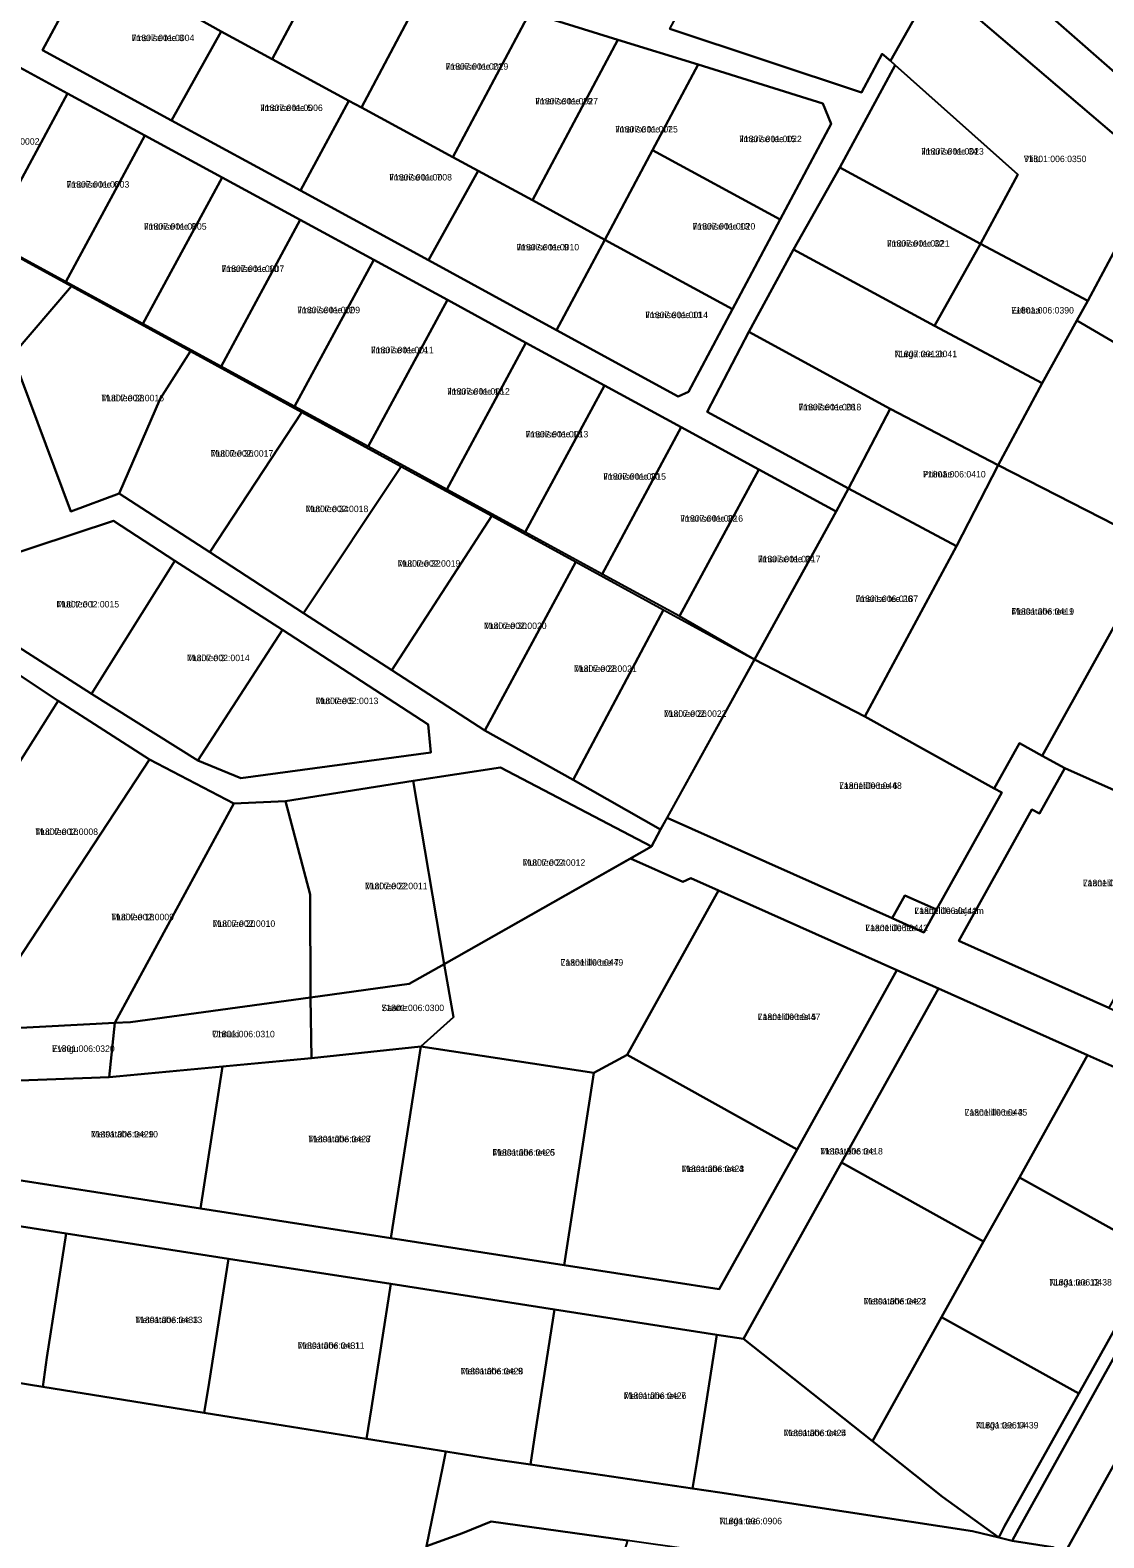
# Model space of a CAD drawing. Extents: x 529768 to 552006, y 6562269 to 6580975.
# Drawn here: x 538116.9 to 538365.3, y 6569572.9 to 6569921.8 of the extents above; entities that cross this region are included whole.
import ezdxf

# ---------------------------------------------------------------- set-up
doc = ezdxf.new("R2010")
doc.units = 0
for name, color, linetype in [('L_AADRESS', 7, 'Continuous'), ('PIIR', 7, 'Continuous'), ('TUNNUS', 7, 'Continuous')]:
    doc.layers.add(name, color=color, linetype=linetype)

msp = doc.modelspace()

# ---------------------------------------------------------------- linework, layer by layer
at = {"layer": 'PIIR'}
for points in [[(538194.78, 6570045.29), (538204.09, 6570052.49), (538294.54, 6569976.3), (538387.81, 6569894.55), (538483.98, 6569812.62), (538481.98, 6569810.6), (538469.84, 6569798.25), (538468.86, 6569806.04), (538468.33, 6569807.76), (538466.92, 6569812.96), (538412.51, 6569859.39), (538377.69, 6569889.12), (538326.28, 6569933.03), (538292.44, 6569961.91), (538270.33, 6569980.79), (538256.38, 6569992.7), (538223.22, 6570021.01)], [(538130.09, 6569936.52), (538119.74, 6569917.12), (538149.59, 6569900.87), (538179.4, 6569884.65), (538209.01, 6569868.54), (538238.69, 6569852.39), (538266.8, 6569836.99), (538269.18, 6569838.12), (538279.4, 6569857.26), (538290.44, 6569877.94), (538302.25, 6569900.12), (538300.32, 6569904.83), (538271.42, 6569913.8), (538252.85, 6569919.57), (538232.51, 6569925.89), (538209.07, 6569933.17), (538191.16, 6569949.28), (538176.18, 6569962.9), (538170.92, 6569967.63), (538167.9, 6569967.7), (538131.41, 6569937.62)], [(538161.09, 6569921.5), (538155.82, 6569924.37), (538176.18, 6569962.9), (538191.16, 6569949.28), (538172.87, 6569915.11)], [(538278.76, 6569947.68), (538292.44, 6569961.91), (538326.28, 6569933.03), (538315.93, 6569914.67), (538314.05, 6569916.29), (538309.25, 6569907.34), (538264.92, 6569922.07)], [(538190.61, 6569905.47), (538172.87, 6569915.11), (538191.16, 6569949.28), (538209.07, 6569933.17), (538193.51, 6569903.91)], [(538155.82, 6569924.37), (538161.09, 6569921.5), (538149.59, 6569900.87), (538119.74, 6569917.12), (538130.09, 6569936.52), (538131.41, 6569937.62)], [(538214.69, 6569892.4), (538193.51, 6569903.91), (538209.07, 6569933.17), (538232.51, 6569925.89)], [(538345.46, 6569888.38), (538317.02, 6569913.66), (538315.93, 6569914.67), (538326.28, 6569933.03), (538377.69, 6569889.14), (538361.67, 6569859.15), (538336.78, 6569872.31)], [(538232.51, 6569925.89), (538252.85, 6569919.57), (538233.08, 6569882.41), (538220.51, 6569889.24), (538214.69, 6569892.4)], [(538172.87, 6569915.11), (538190.61, 6569905.47), (538179.4, 6569884.65), (538149.59, 6569900.87), (538161.09, 6569921.5)], [(538105.9, 6569917.81), (538125.49, 6569907.16), (538107.21, 6569873.27), (538083.52, 6569886.17)], [(538252.85, 6569919.57), (538271.42, 6569913.8), (538260.89, 6569894.03), (538249.87, 6569873.3), (538233.08, 6569882.41)], [(538300.32, 6569904.83), (538302.25, 6569900.12), (538290.44, 6569877.94), (538260.89, 6569894.03), (538271.42, 6569913.8)], [(538317.02, 6569913.66), (538345.46, 6569888.38), (538336.78, 6569872.31), (538304.21, 6569890.03)], [(538125.49, 6569907.16), (538143.39, 6569897.43), (538125.1, 6569863.53), (538107.21, 6569873.27)], [(538179.4, 6569884.65), (538190.61, 6569905.47), (538193.51, 6569903.91), (538214.69, 6569892.4), (538220.51, 6569889.24), (538209.01, 6569868.54)], [(538143.39, 6569897.43), (538161.27, 6569887.71), (538142.97, 6569853.8), (538125.1, 6569863.53)], [(538249.87, 6569873.3), (538260.89, 6569894.03), (538290.44, 6569877.94), (538279.4, 6569857.26)], [(538209.01, 6569868.54), (538220.51, 6569889.24), (538233.08, 6569882.41), (538249.87, 6569873.3), (538238.69, 6569852.39)], [(538293.52, 6569871.07), (538304.21, 6569890.03), (538336.78, 6569872.31), (538326.18, 6569853.35)], [(538361.67, 6569859.15), (538377.69, 6569889.14), (538412.51, 6569859.39), (538410.45, 6569857.04), (538391.66, 6569835.55), (538359.11, 6569854.57)], [(538142.97, 6569853.8), (538161.27, 6569887.71), (538179.34, 6569877.88), (538161.04, 6569843.96)], [(538161.04, 6569843.96), (538179.34, 6569877.88), (538196.37, 6569868.62), (538178.07, 6569834.69)], [(538279.4, 6569857.26), (538269.18, 6569838.12), (538266.8, 6569836.99), (538238.69, 6569852.39), (538249.87, 6569873.3)], [(538336.78, 6569872.31), (538361.67, 6569859.15), (538359.11, 6569854.57), (538351.09, 6569840.13), (538326.18, 6569853.35)], [(538178.07, 6569834.69), (538196.37, 6569868.62), (538213.41, 6569859.36), (538195.1, 6569825.42)], [(538293.52, 6569871.07), (538326.18, 6569853.35), (538351.09, 6569840.13), (538340.87, 6569821.17), (538315.9, 6569834.2), (538283.19, 6569851.95)], [(538112.75, 6569846.55), (538126.45, 6569862.56), (538153.93, 6569847.53), (538146.92, 6569836.49), (538137.49, 6569814.61), (538126.26, 6569810.39)], [(538195.1, 6569825.42), (538213.41, 6569859.36), (538231.59, 6569849.47), (538213.27, 6569815.52)], [(538351.09, 6569840.13), (538359.11, 6569854.57), (538391.66, 6569835.55), (538374.81, 6569803.78), (538340.87, 6569821.17)], [(538315.9, 6569834.2), (538306.24, 6569815.71), (538273.53, 6569833.51), (538283.19, 6569851.95)], [(538137.49, 6569814.61), (538146.92, 6569836.49), (538153.93, 6569847.53), (538179.75, 6569833.42), (538158.46, 6569801)], [(538213.27, 6569815.52), (538231.59, 6569849.47), (538249.77, 6569839.58), (538231.45, 6569805.62)], [(538231.45, 6569805.62), (538249.77, 6569839.58), (538267.55, 6569829.91), (538249.22, 6569795.94)], [(538179.75, 6569833.42), (538202.75, 6569820.85), (538180.13, 6569786.88), (538158.46, 6569801)], [(538315.9, 6569834.2), (538340.87, 6569821.17), (538331.25, 6569802.37), (538306.24, 6569815.71)], [(538249.22, 6569795.94), (538267.55, 6569829.91), (538285.47, 6569820.17), (538267.13, 6569786.19)], [(538180.13, 6569786.88), (538202.75, 6569820.85), (538223.68, 6569809.4), (538200.59, 6569773.67)], [(538267.13, 6569786.19), (538285.47, 6569820.17), (538303.39, 6569810.42), (538284.49, 6569776.16)], [(538340.87, 6569821.17), (538374.81, 6569803.78), (538377.9, 6569802.16), (538351.04, 6569753.92), (538345.8, 6569756.83), (538339.96, 6569746.35), (538310.01, 6569763.02), (538331.25, 6569802.37)], [(538284.49, 6569776.16), (538303.39, 6569810.42), (538306.24, 6569815.71), (538331.25, 6569802.37), (538310.01, 6569763.02)], [(538200.59, 6569773.67), (538223.68, 6569809.4), (538243.17, 6569798.75), (538222.05, 6569759.71)], [(538481.98, 6569810.6), (538487.63, 6569805.85), (538461.57, 6569758.92), (538458.39, 6569753.08), (538452.57, 6569742.7), (538433.7, 6569708.78), (538415.11, 6569675.33), (538409.28, 6569664.76), (538391.55, 6569632.83), (538374.35, 6569601.84), (538359.18, 6569574.54), (538356.27, 6569569.3), (538353.57, 6569570.8), (538344.1, 6569572.28), (538345.65, 6569575.1), (538450.76, 6569763.95), (538469.84, 6569798.25)], [(538136.16, 6569808.23), (538150.33, 6569799.01), (538131.06, 6569768.19), (538103.29, 6569785.94), (538098.94, 6569796.03)], [(538155.69, 6569752.8), (538165.61, 6569748.68), (538209.61, 6569754.66), (538208.94, 6569761.16), (538175.26, 6569783.01), (538150.33, 6569799.01), (538136.16, 6569808.23), (538098.94, 6569796.03), (538103.29, 6569785.94), (538131.06, 6569768.19)], [(538377.9, 6569802.16), (538397.21, 6569792.04), (538414.99, 6569782.72), (538399.06, 6569754.1), (538389.18, 6569736.34), (538356.29, 6569751), (538351.04, 6569753.92)], [(538150.33, 6569799.01), (538175.26, 6569783.01), (538155.69, 6569752.8), (538131.06, 6569768.19)], [(538222.05, 6569759.71), (538243.17, 6569798.75), (538263.42, 6569787.68), (538242.55, 6569748.31)], [(538263.42, 6569787.68), (538284.49, 6569776.16), (538262.76, 6569736.8), (538242.55, 6569748.31)], [(538073.96, 6569739.47), (538100.97, 6569781.45), (538123.36, 6569766.57), (538091.68, 6569716.58)], [(538175.26, 6569783.01), (538208.94, 6569761.16), (538209.61, 6569754.66), (538165.61, 6569748.68), (538155.69, 6569752.8)], [(538284.49, 6569776.16), (538310.01, 6569763.02), (538339.96, 6569746.35), (538341.71, 6569745.38), (538326.63, 6569718.29), (538319.3, 6569721.55), (538316.37, 6569716.29), (538264.26, 6569739.51)], [(538091.68, 6569716.58), (538123.36, 6569766.57), (538144.44, 6569753.03), (538107.27, 6569696.53)], [(538448.11, 6569765.36), (538450.76, 6569763.95), (538345.65, 6569575.1), (538344.1, 6569572.28), (538341.05, 6569573.02), (538342.38, 6569575.61), (538359.59, 6569606.32), (538377.59, 6569638.65), (538394.92, 6569669.8), (538400.66, 6569680.38), (538415.6, 6569707.13), (538431.68, 6569735.94)], [(538264.26, 6569739.51), (538316.37, 6569716.29), (538323.7, 6569713.02), (538326.63, 6569718.29), (538341.71, 6569745.38), (538339.96, 6569746.35), (538345.8, 6569756.83), (538351.04, 6569753.92), (538356.29, 6569751), (538350.45, 6569740.51), (538348.7, 6569741.49), (538331.77, 6569711.07), (538366.5, 6569695.6), (538400.66, 6569680.38), (538394.92, 6569669.8), (538361.56, 6569684.66), (538327.06, 6569700.03), (538317.43, 6569704.32), (538276.16, 6569722.71), (538269.78, 6569725.55), (538267.89, 6569724.75), (538255.8, 6569730.14), (538260.66, 6569732.9), (538262.76, 6569736.8)], [(538107.27, 6569696.53), (538144.44, 6569753.03), (538164.01, 6569742.86), (538136.43, 6569692.07), (538111.76, 6569690.76)], [(538205.51, 6569748.11), (538225.68, 6569751.2), (538260.66, 6569732.9), (538212.68, 6569705.68)], [(538356.29, 6569751), (538389.18, 6569736.34), (538383.01, 6569725.26), (538366.5, 6569695.6), (538331.77, 6569711.07), (538348.7, 6569741.49), (538350.45, 6569740.51)], [(538181.63, 6569721.82), (538175.98, 6569743.41), (538205.51, 6569748.11), (538212.68, 6569705.68), (538204.6, 6569701.11), (538181.7, 6569697.97)], [(538164.01, 6569742.86), (538175.98, 6569743.41), (538181.63, 6569721.82), (538181.7, 6569697.97), (538140.09, 6569692.27), (538136.43, 6569692.07)], [(538212.68, 6569705.68), (538255.8, 6569730.14), (538267.89, 6569724.75), (538269.78, 6569725.55), (538276.16, 6569722.71), (538255.01, 6569684.7), (538247.32, 6569680.53), (538207.24, 6569686.64), (538214.81, 6569693.44)], [(538276.16, 6569722.71), (538317.43, 6569704.32), (538294.33, 6569662.81), (538255.01, 6569684.7)], [(538319.3, 6569721.55), (538326.63, 6569718.29), (538323.7, 6569713.02), (538316.37, 6569716.29)], [(538080.43, 6569660.96), (538101.78, 6569657.64), (538156.29, 6569649.16), (538200.35, 6569642.31), (538240.41, 6569636.07), (538276.33, 6569630.48), (538294.33, 6569662.81), (538317.43, 6569704.32), (538327.06, 6569700.03), (538304.66, 6569659.78), (538281.95, 6569618.98), (538275.78, 6569619.94), (538238.23, 6569625.78), (538200.29, 6569631.68), (538162.74, 6569637.52), (538125.19, 6569643.36), (538092.65, 6569648.42), (538092.11, 6569644.96), (538078.27, 6569647.11)], [(538204.6, 6569701.11), (538212.68, 6569705.68), (538214.81, 6569693.44), (538207.24, 6569686.64), (538181.94, 6569683.95), (538181.7, 6569697.97)], [(538136.43, 6569692.07), (538140.09, 6569692.27), (538181.7, 6569697.97), (538181.94, 6569683.95), (538135.13, 6569679.55)], [(538327.06, 6569700.03), (538361.56, 6569684.66), (538345.8, 6569656.34), (538337.53, 6569641.48), (538304.66, 6569659.78)], [(538105.49, 6569681.5), (538111.76, 6569690.76), (538136.43, 6569692.07), (538135.13, 6569679.55), (538112.43, 6569678.68)], [(538161.4, 6569682.02), (538181.94, 6569683.95), (538207.24, 6569686.64), (538200.35, 6569642.31), (538156.29, 6569649.16)], [(538207.24, 6569686.64), (538247.32, 6569680.53), (538240.41, 6569636.07), (538200.35, 6569642.31)], [(538247.32, 6569680.53), (538255.01, 6569684.7), (538294.33, 6569662.81), (538276.33, 6569630.48), (538240.41, 6569636.07)], [(538361.56, 6569684.66), (538394.92, 6569669.8), (538377.59, 6569638.65), (538345.8, 6569656.34)], [(538105.49, 6569681.5), (538112.43, 6569678.68), (538135.13, 6569679.55), (538161.4, 6569682.02), (538156.29, 6569649.16), (538101.78, 6569657.64)], [(538304.66, 6569659.78), (538337.53, 6569641.48), (538327.8, 6569624.01), (538311.83, 6569595.3), (538281.95, 6569618.98)], [(538345.8, 6569656.34), (538377.59, 6569638.65), (538359.59, 6569606.32), (538327.8, 6569624.01), (538337.53, 6569641.48)], [(538078.27, 6569647.11), (538092.11, 6569644.96), (538092.65, 6569648.42), (538125.19, 6569643.36), (538120.73, 6569614.69), (538119.76, 6569607.91), (538112.71, 6569609.04), (538093.34, 6569612.14), (538073.31, 6569615.34), (538074.42, 6569622.33)], [(538125.19, 6569643.36), (538162.74, 6569637.52), (538158.28, 6569608.86), (538157.16, 6569601.9), (538119.76, 6569607.91), (538120.73, 6569614.69)], [(538158.28, 6569608.86), (538162.74, 6569637.52), (538200.29, 6569631.68), (538195.83, 6569603.03), (538194.71, 6569595.86), (538169.62, 6569599.89), (538157.16, 6569601.9)], [(538200.29, 6569631.68), (538238.23, 6569625.78), (538233.77, 6569597.13), (538232.64, 6569589.88), (538225.06, 6569590.99), (538194.71, 6569595.86), (538195.83, 6569603.03)], [(538238.23, 6569625.78), (538275.78, 6569619.94), (538271.32, 6569591.29), (538270.16, 6569584.4), (538232.64, 6569589.88), (538233.77, 6569597.13)], [(538327.8, 6569624.01), (538359.59, 6569606.32), (538342.38, 6569575.61), (538341.05, 6569573.02), (538328.01, 6569582.47), (538311.83, 6569595.3)], [(538270.16, 6569584.4), (538271.32, 6569591.29), (538275.78, 6569619.94), (538281.95, 6569618.98), (538311.83, 6569595.3), (538328.01, 6569582.47), (538341.05, 6569573.02), (538334.93, 6569574.49), (538276.48, 6569583.47)], [(538374.35, 6569601.84), (538405.82, 6569584.36), (538390.33, 6569556.47), (538387.81, 6569551.93), (538356.27, 6569569.3), (538359.18, 6569574.54)], [(538212.36, 6569589.46), (538213.06, 6569592.91), (538225.06, 6569590.99), (538232.64, 6569589.88), (538270.16, 6569584.4), (538276.48, 6569583.47), (538334.93, 6569574.49), (538341.05, 6569573.02), (538344.1, 6569572.28), (538353.57, 6569570.8), (538352.24, 6569568.28), (538347.47, 6569559.27), (538343.28, 6569559.86), (538299.59, 6569566.02), (538255.09, 6569572.3), (538223.52, 6569576.75), (538216.9, 6569574.06), (538208.58, 6569571.04)], [(538208.58, 6569571.04), (538216.9, 6569574.06), (538223.52, 6569576.75), (538255.09, 6569572.3), (538198.64, 6569390.2), (538173.96, 6569399.94)]]:
    msp.add_lwpolyline(points, close=True, dxfattribs=at)
for points in [[(538463.69, 6569930.51), (538500.26, 6569829.22), (538483.98, 6569812.62), (538387.81, 6569894.55), (538294.54, 6569976.3)], [(538264.92, 6569922.07), (538309.25, 6569907.34), (538314.05, 6569916.29), (538315.93, 6569914.67), (538317.02, 6569913.66), (538304.21, 6569890.03), (538293.52, 6569871.07), (538283.19, 6569851.95), (538273.53, 6569833.51), (538306.24, 6569815.71), (538303.39, 6569810.42), (538285.47, 6569820.17), (538267.55, 6569829.91), (538249.77, 6569839.58), (538231.59, 6569849.47), (538213.41, 6569859.36), (538196.37, 6569868.62), (538179.34, 6569877.88), (538161.27, 6569887.71), (538143.39, 6569897.43), (538125.49, 6569907.16), (538105.9, 6569917.81)], [(538033.76, 6569913.23), (538126.45, 6569862.56), (538112.75, 6569846.55), (538126.26, 6569810.39), (538137.49, 6569814.61), (538158.46, 6569801), (538180.13, 6569786.88), (538200.59, 6569773.67), (538222.05, 6569759.71), (538242.55, 6569748.31), (538262.76, 6569736.8), (538260.66, 6569732.9), (538225.68, 6569751.2), (538205.51, 6569748.11), (538175.98, 6569743.41), (538164.01, 6569742.86), (538144.44, 6569753.03), (538123.36, 6569766.57), (538100.97, 6569781.45)], [(538112.71, 6569609.04), (538119.76, 6569607.91), (538157.16, 6569601.9), (538169.62, 6569599.89), (538194.71, 6569595.86), (538213.06, 6569592.91), (538212.36, 6569589.46), (538208.58, 6569571.04), (538173.96, 6569399.94), (538198.64, 6569390.2), (538221.78, 6569381.06), (538236.86, 6569375.1), (538239.69, 6569373.99), (538240.87, 6569373.65), (538242.38, 6569373.72), (538244.02, 6569374.31), (538245.03, 6569375.08), (538245.95, 6569376.29), (538343.28, 6569559.86), (538347.47, 6569559.27), (538262.64, 6569398.41), (538232.72, 6569343.23), (538167.92, 6569228.94), (538087.24, 6569085.89)]]:
    msp.add_lwpolyline(points, dxfattribs=at)

# ---------------------------------------------------------------- texts
at = {"layer": 'L_AADRESS'}
for s, p in [('Ilmarise tee 3', (538140.35, 6569919.25)), ('Ilmarise tee 21', (538213.01, 6569912.63)), ('Ilmarise tee 19', (538233.77, 6569904.6)), ('Ilmarise tee 5', (538170.07, 6569903.07)), ('Ilmarise tee 17', (538252.25, 6569898.11)), ('Ilmarise tee 15', (538280.93, 6569895.87)), ('Ilmarise tee 34', (538323.05, 6569892.99)), ('Viilu', (538346.81, 6569891.25)), ('Ilmarise tee 6', (538125.3, 6569885.35)), ('Ilmarise tee 7', (538199.97, 6569887)), ('Ilmarise tee 8', (538143.19, 6569875.62)), ('Ilmarise tee 13', (538270.17, 6569875.65)), ('Ilmarise tee 9', (538229.41, 6569870.82)), ('Ilmarise tee 32', (538315.15, 6569871.69)), ('Ilmarise tee 10', (538161.16, 6569865.84)), ('Ilmarise tee 12', (538178.7, 6569856.29)), ('Eelmaa', (538343.91, 6569856.22)), ('Ilmarise tee 11', (538259.22, 6569855.15)), ('Ilmarise tee 14', (538195.74, 6569847.03)), ('Nurga tee 2b', (538316.87, 6569846.12)), ('Muti tee 38', (538133.34, 6569835.92)), ('Ilmarise tee 16', (538213.35, 6569837.45)), ('Ilmarise tee 28', (538294.7, 6569833.83)), ('Ilmarise tee 18', (538231.52, 6569827.55)), ('Muti tee 36', (538158.62, 6569823.11)), ('Ilmarise tee 20', (538249.5, 6569817.77)), ('Priimäe', (538323.49, 6569818.29)), ('Muti tee 34', (538180.61, 6569810.27)), ('Ilmarise tee 22', (538267.34, 6569808.06)), ('Muti tee 32', (538201.91, 6569797.64)), ('Ilmarise tee 24', (538285.26, 6569798.67)), ('Ilmarise tee 26', (538307.87, 6569789.48)), ('Muti tee 1', (538122.94, 6569788.21)), ('Metsatähe tee 1', (538343.95, 6569786.55)), ('Muti tee 30', (538221.88, 6569783.22)), ('Muti tee 3', (538153.16, 6569775.79)), ('Muti tee 28', (538242.73, 6569773.3)), ('Muti tee 5', (538182.93, 6569765.85)), ('Muti tee 26', (538263.52, 6569762.9)), ('Laanelille tee 6', (538304.08, 6569746.23)), ('Muti tee 16', (538118.06, 6569735.57)), ('Muti tee 24', (538230.82, 6569728.44)), ('Laanelille tee 4', (538360.48, 6569723.71)), ('Muti tee 22', (538194.33, 6569723.02)), ('Laanelille alajaam', (538321.5, 6569717.29)), ('Muti tee 18', (538135.64, 6569715.84)), ('Muti tee 20', (538159.07, 6569714.31)), ('Laanelille tee', (538310.14, 6569713.32)), ('Laanelille tee 7', (538239.62, 6569705.34)), ('Saarte', (538198.16, 6569694.82)), ('Laanelille tee 5', (538285.25, 6569692.76)), ('Unnuki', (538158.97, 6569688.76)), ('Evingu', (538121.92, 6569685.38)), ('Laanelille tee 3', (538333.11, 6569670.64)), ('Metsatähe tee 10', (538130.93, 6569665.59)), ('Metsatähe tee 8', (538181.23, 6569664.48)), ('Metsatähe tee 6', (538223.84, 6569661.38)), ('Metsatähe tee', (538299.69, 6569661.65)), ('Metsatähe tee 4', (538267.59, 6569657.59)), ('Nurga tee 12', (538352.7, 6569631.33)), ('Metsatähe tee 3', (538309.74, 6569626.95)), ('Metsatähe tee 13', (538141.19, 6569622.63)), ('Metsatähe tee 11', (538178.73, 6569616.69)), ('Metsatähe tee 9', (538216.47, 6569610.78)), ('Metsatähe tee 7', (538254.24, 6569605.09)), ('Nurga tee 14', (538335.71, 6569598.25)), ('Metsatähe tee 5', (538291.23, 6569596.48)), ('Nurga tee', (538276.36, 6569576.09))]:
    msp.add_text(s, height=1.5, dxfattribs=at).set_placement(p)
at = {"layer": 'TUNNUS'}
for s, p in [('71807:001:0004', (538140.35, 6569919.25)), ('71807:001:0029', (538213.01, 6569912.63)), ('71807:001:0027', (538233.77, 6569904.6)), ('71807:001:0006', (538170.07, 6569903.07)), ('71807:001:0025', (538252.25, 6569898.11)), ('71807:001:0002', (538104.51, 6569895.29)), ('71807:001:0022', (538280.93, 6569895.87)), ('71807:001:0023', (538323.05, 6569892.99)), ('71801:006:0350', (538346.81, 6569891.25)), ('71807:001:0003', (538125.3, 6569885.35)), ('71807:001:0008', (538199.97, 6569887)), ('71807:001:0005', (538143.19, 6569875.62)), ('71807:001:0020', (538270.17, 6569875.65)), ('71807:001:0010', (538229.41, 6569870.82)), ('71807:001:0021', (538315.15, 6569871.69)), ('71807:001:0007', (538161.16, 6569865.84)), ('71807:001:0009', (538178.7, 6569856.29)), ('71801:006:0390', (538343.91, 6569856.22)), ('71807:001:0014', (538259.22, 6569855.15)), ('71807:001:0011', (538195.74, 6569847.03)), ('71807:001:0041', (538316.87, 6569846.12)), ('71807:002:0016', (538133.34, 6569835.92)), ('71807:001:0012', (538213.35, 6569837.45)), ('71807:001:0018', (538294.7, 6569833.83)), ('71807:001:0013', (538231.52, 6569827.55)), ('71807:002:0017', (538158.62, 6569823.11)), ('71807:001:0015', (538249.5, 6569817.77)), ('71801:006:0410', (538323.49, 6569818.29)), ('71807:002:0018', (538180.61, 6569810.27)), ('71807:001:0016', (538267.34, 6569808.06)), ('71807:002:0019', (538201.91, 6569797.64)), ('71807:001:0017', (538285.26, 6569798.67)), ('71801:006:0187', (538307.87, 6569789.48)), ('71807:002:0015', (538122.94, 6569788.21)), ('71801:006:0419', (538343.95, 6569786.55)), ('71807:002:0020', (538221.88, 6569783.22)), ('71807:002:0014', (538153.16, 6569775.79)), ('71807:002:0021', (538242.73, 6569773.3)), ('71807:002:0013', (538182.93, 6569765.85)), ('71807:002:0022', (538263.52, 6569762.9)), ('71801:006:0448', (538304.08, 6569746.23)), ('71807:002:0008', (538118.06, 6569735.57)), ('71807:002:0012', (538230.82, 6569728.44)), ('71801:006:0446', (538360.48, 6569723.71)), ('71807:002:0011', (538194.33, 6569723.02)), ('71801:006:0441', (538321.5, 6569717.29)), ('71807:002:0009', (538135.64, 6569715.84)), ('71807:002:0010', (538159.07, 6569714.31)), ('71801:006:0442', (538310.14, 6569713.32)), ('71801:006:0449', (538239.62, 6569705.34)), ('71801:006:0300', (538198.16, 6569694.82)), ('71801:006:0447', (538285.25, 6569692.76)), ('71801:006:0310', (538158.97, 6569688.76)), ('71801:006:0320', (538121.92, 6569685.38)), ('71801:006:0445', (538333.11, 6569670.64)), ('71801:006:0429', (538130.93, 6569665.59)), ('71801:006:0427', (538181.23, 6569664.48)), ('71801:006:0425', (538223.84, 6569661.38)), ('71801:006:0418', (538299.69, 6569661.65)), ('71801:006:0423', (538267.59, 6569657.59)), ('71801:006:0438', (538352.7, 6569631.33)), ('71801:006:0422', (538309.74, 6569626.95)), ('71801:006:0433', (538141.19, 6569622.63)), ('71801:006:0431', (538178.73, 6569616.69)), ('71801:006:0428', (538216.47, 6569610.78)), ('71801:006:0426', (538254.24, 6569605.09)), ('71801:006:0439', (538335.71, 6569598.25)), ('71801:006:0424', (538291.23, 6569596.48)), ('71801:006:0906', (538276.36, 6569576.09))]:
    msp.add_text(s, height=1.5, dxfattribs=at).set_placement(p)

doc.saveas('drawing.dxf')
